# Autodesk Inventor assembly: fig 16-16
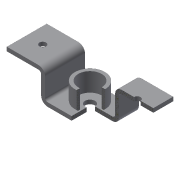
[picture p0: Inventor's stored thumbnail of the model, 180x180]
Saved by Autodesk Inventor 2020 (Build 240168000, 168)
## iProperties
Created: 2005-03
Part Number: fig 16-16
Document SubType Name: Weldment
Designer: CADCIM
Manufacturer: Standard
Standards Organization: Custom
Author: CADCIM
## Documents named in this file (3)
- D:\Autodesk Inventor_2020\Resources\Resources\Inventor_2020_Part\Inventor_2020_Part\c16_Inv_2020_prt\fig 16-16\fig 16-16.iam
- D:\Autodesk Inventor_2020\Resources\Resources\Inventor_2020_Part\Inventor_2020_Part\c16_Inv_2020_prt\fig 16-16\Bracket.ipt
- D:\Autodesk Inventor_2020\Resources\Resources\Inventor_2020_Part\Inventor_2020_Part\c16_Inv_2020_prt\fig 16-16\cylinder.ipt
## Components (2 placed, 2 different names)
1. Bracket:1 — Insert:1
2. cylinder:1 — Insert:1
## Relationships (1: Insert 1)
- Insert:1: Bracket:1 ↔ cylinder:1
